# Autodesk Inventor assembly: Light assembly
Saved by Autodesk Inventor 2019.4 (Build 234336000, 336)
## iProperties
Created: 2019-12
Part Number: Light assembly
Document SubType Name: Assembly
Designer: Administrator
Title: Light assembly v3
Author: Administrator
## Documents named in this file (3)
- c:\worker\convert-fusion-r09\tmp\job-1\3\output\files\e4c84826-0180-4e22-b740-8a53e6050974\Light assembly v3.iam
- c:\worker\convert-fusion-r09\tmp\job-1\3\output\files\e4c84826-0180-4e22-b740-8a53e6050974\Led strip v1.ipt
- c:\worker\convert-fusion-r09\tmp\job-1\3\output\files\e4c84826-0180-4e22-b740-8a53e6050974\Light connects v4.ipt
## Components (4 placed, 2 different names)
1. Led strip v1:1
2. Light connects v4:1
3. Led strip v1:2
4. Led strip v1:3
